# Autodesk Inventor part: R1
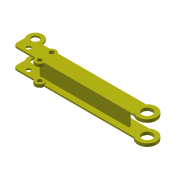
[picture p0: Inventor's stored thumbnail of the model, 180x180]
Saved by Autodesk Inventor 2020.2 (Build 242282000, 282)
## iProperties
Created: 2005-10
Part Number: R1
Document SubType Name: Modeling
Designer: F.Stasiak
Density: 1 g/cm^3
Material: Ogólny
Appearance: Żółta
Manager: www.cadconsulting.pl
Company: Fabian Stasiak CAD Consulting
Author: F.Stasiak
Subject: Zbiór ćwiczeń. Autodesk Inventor 2020. Kurs podstawowy
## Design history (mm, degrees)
sketch "Szkic1"
  geometry: L1 (-448.745, 481.719)-(-2248.745, 481.719); L2 (-2248.745, 281.719)-(-448.745, 281.719); L3 (-2248.745, 281.719)-(-2248.745, 481.719); L4 (-448.745, 281.719)-(-448.745, 481.719)
  constraints: 8 end point, 2 parallel, 1 horizontal, 1 perpendicular
  dimensions: "d0" = 1800 distance of L1.start L1.end
extrude "Wyciągnięcie proste1" new body sketch "Szkic1" stored distance "d2" = 240; taper "d3" = 0 deg
fillet "Zaokrąglenie2" dims "d40" = 100
feature "Skorupa2" dims "d41" = 20
sketch "Szkic5"
  geometry: C1 r 60 at (1890.832, 281.719); C2 r 50 at (1890.832, 281.719) reference
  constraints: 1 centre point, 1 coincident
  dimensions: "d94" = 120 diameter of C1
extrude "Wyciągnięcie proste5" join sketch "Szkic5" distance "d43" = 40; taper "d44" = 0 deg
sketch "Szkic7"
  geometry: L1 (548.745, 481.719)-(2248.745, 481.719) reference; L2 (2248.745, 481.719)-(2248.745, 281.719) reference; C1 r 100 at (2168.745, 501.719)
  constraints: 1 centre point
  dimensions: "d52" = 200 diameter of C1; "d53" = 20 distance from line of L1 C1.centre; "d54" = 80 distance from line of L2 C1.centre
extrude "Wyciągnięcie proste6" join sketch "Szkic7" distance "d55" = 20; taper "d56" = 0 deg
sketch "Szkic8"
  geometry: L1 (548.745, 481.719)-(2070.765, 481.719) reference; C1 r 60 at (1890.832, 281.719) reference; C2 r 60 at (1901.883, 451.719); C3 r 50 at (1901.883, 451.719) reference
  constraints: 1 centre point, 1 coincident, 1 equal radius
  dimensions: "d95" = 120 diameter of C2 (derived)
extrude "Wyciągnięcie proste7" join sketch "Szkic8" distance "d58" = 40; taper "d59" = 0 deg
sketch "Szkic9"
  geometry: L1 (0, 200)-(1700, 200) reference; L2 (220, 100)-(1420, 100); L3 (1420, 100)-(1420, 75); L4 (1420, 75)-(220, 75); L5 (220, 75)-(220, 100); A1 r 100 centre (0, 100) between (0, 200) and (0, 0) reference
  constraints: 8 end point, 2 parallel, 1 horizontal, 1 perpendicular
  dimensions: "d60" = 25 distance of L4.end L2.start; "d61" = 100 distance between parallel lines of L1 L2; "d62" = 1200 distance of L3.end L4.end; "d63" = 220 distance from line of A1.centre L5
extrude "Wyciągnięcie proste8" join sketch "Szkic9" stored distance "d64" = 10; taper "d65" = 0 deg
sketch "Szkic10"
  geometry: C1 r 125 at (548.745, 381.719); A1 r 100 centre (548.745, 381.719) between (548.745, 481.719) and (548.745, 281.719) reference
  constraints: 1 centre point, 1 coincident
  dimensions: "d66" = 250 diameter of C1
extrude "Wyciągnięcie proste9" join sketch "Szkic10" stored distance "d67" = 40; taper "d68" = 0 deg
fillet "Zaokrąglenie3" dims "d69" = 20, "d70" = 50
mirror "Lustro2"
hole "Otwór2" diameter "d73" = 140; stored, may be unused: countersink angle "d77" = 90 deg, drill point angle "d79" = 118 deg; dims "d71" = 10, "d72" = 10, "d74" = 6, "d75" = 4, "d76" = 2, "d78" = 8
sketch "Szkic12"
  geometry: A1 r 60 centre (1890.832, 281.719) between (1830.832, 281.719) and (1950.832, 281.719) reference; A2 r 60 centre (1901.883, 451.719) between (1953.845, 481.719) and (1849.922, 481.719) reference
hole "Otwór3" sketch "Szkic12" at (1890.832, 281.719), (1901.883, 451.719) diameter "d80" = 60; stored, may be unused: countersink angle "d84" = 90 deg, drill point angle "d86" = 118 deg; dims "d81" = 6, "d82" = 4, "d83" = 2, "d85" = 8
sketch "Szkic13"
  geometry: A1 r 100 centre (2168.745, 501.719) between (2252.078, 446.442) and (2068.745, 501.719) reference
hole "Otwór4" sketch "Szkic13" at (2168.745, 501.719) diameter "d87" = 100; stored, may be unused: countersink angle "d91" = 90 deg, drill point angle "d93" = 118 deg; dims "d88" = 6, "d89" = 4, "d90" = 2, "d92" = 8
sketch "Szkic14"
  geometry: 1 further point
hole "Otwór5" sketch "Szkic14" at (2109.439, 351.788) diameter "d96" = 60; stored, may be unused: countersink angle "d100" = 90 deg, drill point angle "d102" = 118 deg; dims "d97" = 6, "d98" = 4, "d99" = 2, "d101" = 8
node "Bryła1"
node "Korpusy bryłowe"
node "Korpusy powierzchniowe"
node "Odniesienie2"
node "Odniesienie3"
